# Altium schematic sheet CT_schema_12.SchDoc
size 145 x 119 mm
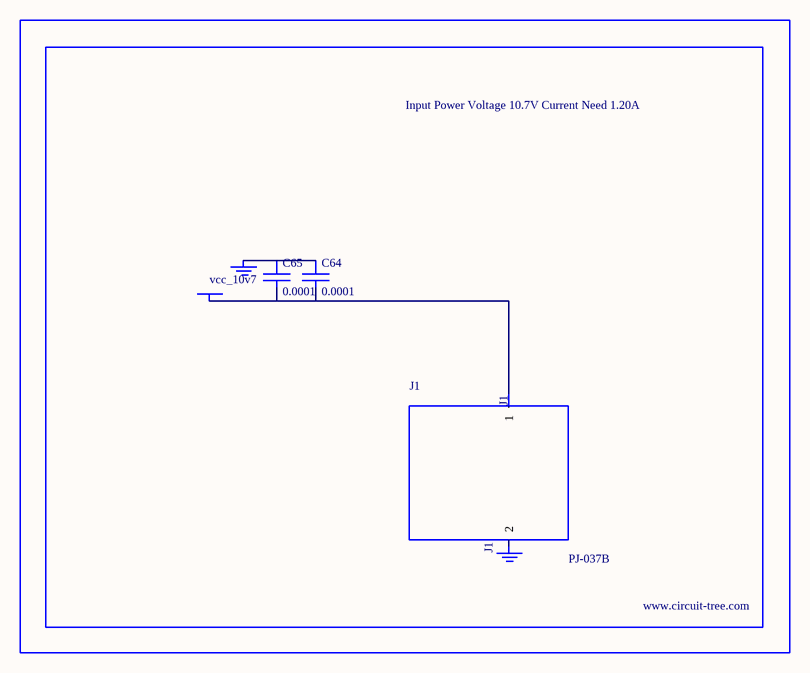
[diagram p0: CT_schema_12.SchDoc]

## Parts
BORDER11  (no value)
C64  0.0001  [EXV-9H]
C65  0.0001  [EXV-9H]
GND_INSTANCE_11_0  (no value)
GND_INSTANCE_11_1  (no value)
J1  PJ-037B  [PJ-037B_PACKAGE]
POWER_INSTANCE_11_0  vcc_10v7

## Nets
NetC64_1: C64.1 C65.1 GND_INSTANCE_11_0.0(GND)
NetC64_2: C64.2 C65.2 J1.1 POWER_INSTANCE_11_0.0(PWR)

Not connected (* = marked no-connect by the designer): GND_INSTANCE_11_1 0(GND); J1 2

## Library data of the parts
BORDER11 = BORDER_PAGE11
C64 C65 = EDK107M035A9HAA
GND_INSTANCE_11_0 GND_INSTANCE_11_1 = GND
POWER_INSTANCE_11_0 = PWR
